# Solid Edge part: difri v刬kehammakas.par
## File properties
Author: Türk
Template: Iso Part.par
Last saved by: Türk
Revision: 10
Application: Solid Edge
Accuracy: 0,990
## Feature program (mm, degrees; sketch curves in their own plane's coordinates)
pattern "PatternOccurrence_1"  XOffset = 11.25 deg
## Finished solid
Body 1: solid body, 280 faces, 688 edges, 410 vertices.
  Faces by surface: plane 176, spline 63, cone 32, cylinder 9
  Edges by curve: line 290, curve on surface 252, circle 145, intersection 1
Bounding box of the edges (mm; curved faces can reach further): 103.826 x 285.000 x 103.826, from (-51.9131, -285, -51.9131) to (51.9131, 0, 51.9131).
Cylindrical faces by radius (mm): R7.5 x2, R10 x4, R27.5 x1, R32 x1, R47.0272 x1
Conical faces (half-angle, radius in mm at the cone's reference point): 45 deg R32 x32
Planar faces by outward normal: +x 2, +y 34, +z 2, -x 2, -y 36, -z 2, oblique 98
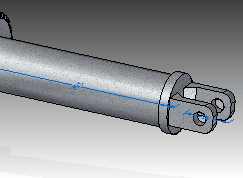
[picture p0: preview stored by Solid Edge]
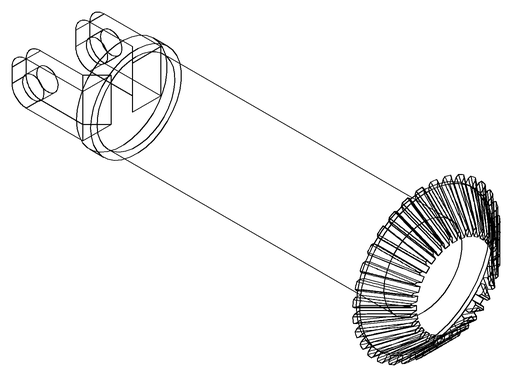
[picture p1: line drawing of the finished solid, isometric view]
